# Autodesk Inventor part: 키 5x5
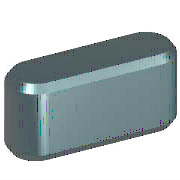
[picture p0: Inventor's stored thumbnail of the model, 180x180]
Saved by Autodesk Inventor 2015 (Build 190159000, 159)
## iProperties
IsCustomPart: 1
Created: 2012-02
Part Number: 키 5x5
Material: 강철, 연강
Description: 키 및 해당 키홈
Document SubType Name: Modeling
Standard: KS B 1311
Designer: mduedu
Standards Organization: KS
Language: ko-KR
Size Designation: 5 x 5 x 12
Categories: <MemberInstance><Categories><Category DisplayName="샤프트 부품" InternalName="7f7aeb1f-a693-4053-b835-cee3144e0d98" Mnemonic="SHFT"><Category DisplayName="키" Interna
Density: 1 g/cm^3
Appearance: 노란색
Author: mduedu
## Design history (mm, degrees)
workplane "Work Plane1"
workplane "Work Plane2"
sketch "스케치1"
  geometry: L1 (2.5, 2.5)-(9.5, 2.5); L2 (9.5, -2.5)-(2.5, -2.5); L3 (0, 9.4)-(0, -7.4) reference; L4 (-5, 0)-(30, 0) reference; L5 (12, 0)-(12, 7); A1 r 2.5 centre (2.5, 0) between (2.5, 2.5) and (2.5, -2.5); A2 r 2.5 centre (9.5, 0) between (9.5, -2.5) and (9.5, 2.5)
  constraints: 6 end point, 5 point on circle, 4 tangent, 3 point on line, 2 centre point, 1 horizontal, 1 parallel, 1 perpendicular
  dimensions: "d0" = 2.5 radius of A1 (= 0.5 x PB); "d13" = 2.5 radius of A2 (= 0.5 x PB); "d14" = 12 distance between parallel lines of L5 L3 (= NLG)
extrude "본체1" new body sketch "스케치1" taper "d3" = 0 deg; stored distance "d4" = 10
workplane "Work Plane3"
body "Solid1"
chamfer "모따기1" distance "d8" = 0.4 (= PHH); stored, may be unused: second distance "d9" = 0.4 (= PHH), angle "d15" = 45 deg
other parameters: "d1" = -3 (= -PNT), "d2" = 2 (= PH - PNT), "NLG" = 12 [user parameter; used in 3 equation terms], "PB" = 5 [user parameter; used in 2 equation terms], "PNT" = 3 [user parameter; used in 2 equation terms], "PH" = 5 [user parameter; used in 1 equation term], "PHH" = 0.4 [user parameter; used in 2 equation terms], "d10" = 0, "d16" = 0, "d17" = 0, "d18" = 0, "WDMIN" = 12 [user parameter], "PLB2" = 12 (= NLG) [user parameter], "WDMAX" = 17 [user parameter], "PLB1" = 12 (= NLG) [user parameter], "RR" = 0.16 [user parameter], "PUEB" = 2.3 [user parameter]
